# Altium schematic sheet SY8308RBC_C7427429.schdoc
size 127 x 101 mm
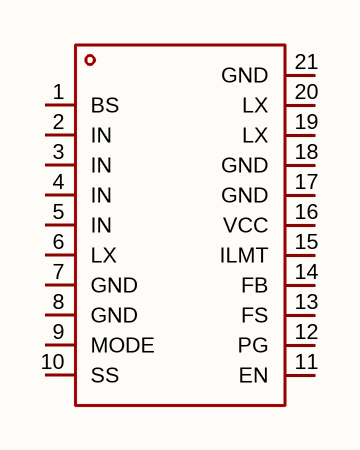
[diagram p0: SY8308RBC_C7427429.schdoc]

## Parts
U?  sy8308rbc_c7427429  [QFN-20_L3.5-W3.5-P0.50-BL-EP1.2]  (value not drawn)

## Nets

Not connected (* = marked no-connect by the designer): U? 1(BS) 2(IN) 3(IN) 4(IN) 5(IN) 6(LX) 7(GND) 8(GND) 9(MODE) 10(SS) 11(EN) 12(PG) 13(FS) 14(FB) 15(ILMT) 16(VCC) 17(GND) 18(GND) 19(LX) 20(LX) 21(GND)

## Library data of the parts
U? = sy8308rbc_c7427429: 功能类型:降压型;工作电压:4V~40V;输出电压:-;输出电流:8A;输出类型:可调;; Manufacturer: Silergy(矽力杰); AddInBom: yes; ModelId: a9932c60cb724a6f8b4579238ed91694; ModelTransform: 137.795,137.795,0,0,0,0,0,0,0; Function: 降压型; Voltage - Supply: 4V~40V; Output Current: 8A; Frequency - Switching: 350kHz；500kHz; Synchronous Rectifier: 是; Number of Outputs: 1; Topology: 降压式; Quiescent Current: 60uA; Switch tube (built-in/external): 内置; Output Type: 可调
